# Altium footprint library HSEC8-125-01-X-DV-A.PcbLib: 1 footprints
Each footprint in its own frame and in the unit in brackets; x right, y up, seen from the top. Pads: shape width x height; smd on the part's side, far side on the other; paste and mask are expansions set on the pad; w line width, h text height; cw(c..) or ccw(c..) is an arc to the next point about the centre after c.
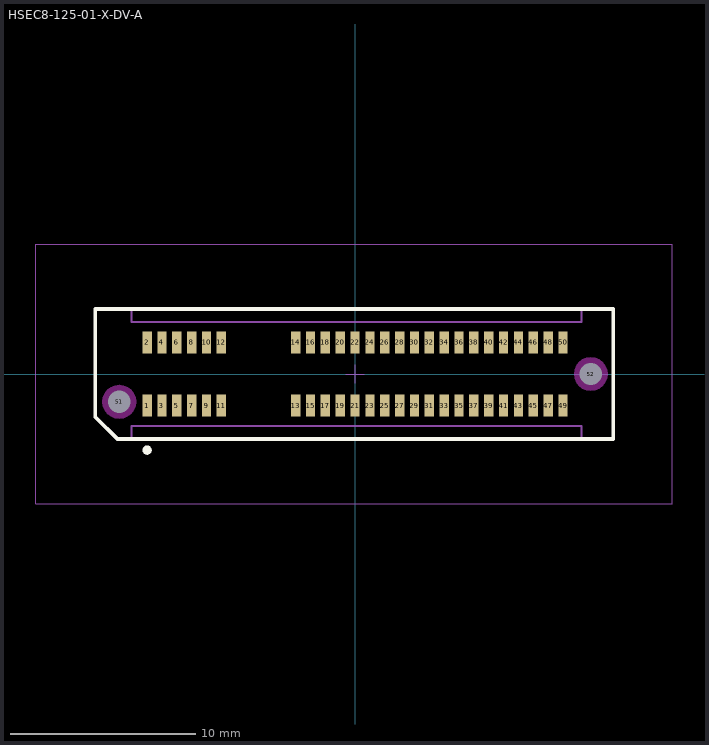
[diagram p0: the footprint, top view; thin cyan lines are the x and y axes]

## HSEC8-125-01-X-DV-A [mm] "0.80mm pitch, 50 pin, hi-speed micro edge card; w/alignment pins"
height 7.98
pads (52):
  rect 0.5x1.2 smd mask+0: 1(-11.2,-1.7) 2(-11.2,1.7) 3(-10.4,-1.7) 4(-10.4,1.7) 5(-9.6,-1.7) 6(-9.6,1.7) 7(-8.8,-1.7) 8(-8.8,1.7) 9(-8,-1.7) 10(-8,1.7) 11(-7.2,-1.7) 12(-7.2,1.7) 13(-3.2,-1.7) 14(-3.2,1.7) 15(-2.4,-1.7) 16(-2.4,1.7) 17(-1.6,-1.7) 18(-1.6,1.7) 19(-0.8,-1.7) 20(-0.8,1.7) 21(0,-1.7) 22(0,1.7) 23(0.8,-1.7) 24(0.8,1.7) 25(1.6,-1.7) 26(1.6,1.7) 27(2.4,-1.7) 28(2.4,1.7) 29(3.2,-1.7) 30(3.2,1.7) 31(4,-1.7) 32(4,1.7) 33(4.8,-1.7) 34(4.8,1.7) 35(5.6,-1.7) 36(5.6,1.7) 37(6.4,-1.7) 38(6.4,1.7) 39(7.2,-1.7) 40(7.2,1.7) 41(8,-1.7) 42(8,1.7) 43(8.8,-1.7) 44(8.8,1.7) 45(9.6,-1.7) 46(9.6,1.7) 47(10.4,-1.7) 48(10.4,1.7) 49(11.2,-1.7) 50(11.2,1.7)
  round 0.5 hole 1.2 unplated mask+0: 51(-12.7,-1.5) 52(12.7,0)
Top Overlay:
  circle w0.25: c-11.2,-4.1 r0.125
  lines w0.2: -14,-2.3 -12.8,-3.5 13.9,-3.5 13.9,3.5 -14,3.5 -14,-2.3
Keep-Out Layer:
  pour cut-out: -11.792,-1.5 -11.823,-1.265 -11.914,-1.046 -12.058,-0.858 -12.246,-0.714 -12.465,-0.623 -12.7,-0.592 -12.935,-0.623 -13.154,-0.714 -13.342,-0.858 -13.486,-1.046 -13.577,-1.265 -13.608,-1.5 -13.577,-1.735 -13.486,-1.954 -13.342,-2.142 -13.154,-2.286 -12.935,-2.377 -12.7,-2.408 -12.465,-2.377 -12.246,-2.286 -12.058,-2.142 -11.914,-1.954 -11.823,-1.735
  pour cut-out: 13.608,0 13.577,0.235 13.486,0.454 13.342,0.642 13.154,0.786 12.935,0.877 12.7,0.908 12.465,0.877 12.246,0.786 12.058,0.642 11.914,0.454 11.823,0.235 11.792,0 11.823,-0.235 11.914,-0.454 12.058,-0.642 12.246,-0.786 12.465,-0.877 12.7,-0.908 12.935,-0.877 13.154,-0.786 13.342,-0.642 13.486,-0.454 13.577,-0.235
Mechanical 12:
  lines w0.001: -14,-2.3 -12.8,-3.5 13.9,-3.5 13.9,3.5 -14,3.5 -14,-2.3
Mechanical 13:
  lines w0.1: -14,-2.3 -12.8,-3.5 -12.05,-3.5 -12.05,-2.794 12.2,-2.794 12.2,-3.5 13.9,-3.5 13.9,3.5 12.2,3.5 12.2,2.8 -12.05,2.8 -12.05,3.5 -14,3.5 -14,-2.3
  text ".Designator" at 0.254,0.254 h1.52
Mechanical 15:
  lines w0.05: -0.5,0 0.5,0 ; 0,-0.5 0,0.5 ; -17.194,-7 17.08,-7 17.08,7 -17.194,7 -17.194,-7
